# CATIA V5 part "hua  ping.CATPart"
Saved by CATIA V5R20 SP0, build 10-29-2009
Part number: Part2
Material "Blue Onyx": density 2770 kg/m3, Young's modulus 6e+10 Pa, Poisson ratio 0.27, thermal expansion 7e-06 1/K
Material "Grass": density 350 kg/m3
Bounding box of the stored display mesh (mm): x -46.351 to 39.989, y -39.989 to 39.949, z 0 to 161.792
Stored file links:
  C:\Users\HUAWEI\Desktop\hua  ping.CATPart
  D:\CATIA20\win_b64\startup\materials\Catalog.CATMaterial
  D:\CATIA20\win_b64\startup\materials\blue_onyx.jpg
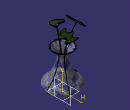
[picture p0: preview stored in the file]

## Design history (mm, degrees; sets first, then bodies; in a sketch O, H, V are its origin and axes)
Set1
  Plane1: type Offset, RefPlane xy-plane, Offset 20
  Plane2: type Offset, RefPlane Plane1, Offset 20
  Plane3: type Offset, RefPlane Plane2, Offset 20
  Plane4: type Offset, RefPlane Plane3, Offset 20
  Plane5: type Offset, RefPlane Plane4, Offset 20
  Sketch1 on xy-plane, origin (0, 0, 0), H (1, 0, 0), V (0, 1, 0)
    circle A1 centre (0, 0) radius 10
  Sketch2 on Plane1, origin (0, 0, 20), H (1, 0, 0), V (0, 1, 0)
    circle A1 centre (0, 0) radius 40
  Sketch3 on Plane2, origin (0, 0, 40), H (1, 0, 0), V (0, 1, 0)
    circle A1 centre (0, 0) radius 24
  Sketch4 on Plane3, origin (0, 0, 60), H (1, 0, 0), V (0, 1, 0)
    circle A1 centre (0, 0) radius 15
  Sketch5 on Plane4, origin (0, 0, 80), H (1, 0, 0), V (0, 1, 0)
    circle A1 centre (0, 0) radius 10
  Sketch6 on Plane5, origin (0, 0, 100), H (1, 0, 0), V (0, 1, 0)
    circle A1 centre (0, 0) radius 25
Body1 (main body), material "Blue Onyx"
  Loft1: solid, Sections (Sketch6; Sketch5; Sketch4; Sketch3; Sketch2; Sketch1)
  Shell1: IntOffset 1, Face face of Loft1, ExtOffset 0
  Sketch7 on yz-plane, origin (0, 0, 0), H (0, 1, 0), V (0, 0, 1)
    axis line L1 (0, 122.4223) -> (0, -28.4493)
  Sketch8 on yz-plane, origin (0, 0, 0), H (0, 1, 0), V (0, 0, 1)
    axis line L1 (0, 133.8174) -> (0, -23.2075)
  Sketch9 on yz-plane, origin (0, 0, 0), H (0, 1, 0), V (0, 0, 1)
    point P1 (0, 32.7739)
    line L1 (0, 32.7739) -> (22.7213, 32.7739)
    arc A1 centre (20.8479, 20.9105) radius 12.0104 from (22.7213, 32.7739) to (25.6844, 9.917) cw
    line L2 (25.6844, 9.917) -> (13.0754, 4.3697)
    line L3 (13.0754, 4.3697) -> (0, 4.3697)
    point P6 (0, 4.3697)
    coincidence: P1 V, P6 V
    horizontal: L1 H, L3 H
    tangency: L2 A1
  Shaft1: profile Sketch9, axis Sketch9.V, angle 360
Body2, material "Grass"
  Sketch10 on yz-plane, origin (0, 0, 0), H (0, 1, 0), V (0, 0, 1)
    spline S1 through (7.8895, 8.5551) (2.3376, 62.8541) (16.0968, 126.7636)
  Plane6: type Normal, Curve Sketch10, RefPoint vertex of Sketch10
  Sketch11 on Plane6, origin (0, 45.3156, 115.2778), H (1, 0, 0), V (0, -0.9307, 0.3658)
    circle A1 centre (0, 31.3229) radius 1
    point P1 (0, 31.3229)
    radius A1 = 1
    coincidence: P1 V
  Rib1: profile Sketch11, centre curve Sketch10
  Sketch12 on Plane6, origin (0, 45.3156, 115.2778), H (1, 0, 0), V (0, -0.9307, 0.3658)
    spline S1 through (-9.4387, 50.7533) (-6.6792, 39.3585) (-16.8312, 37.3892) (-6.6792, 28.5159) (-15.19, 22.2241) (-5.7623, 21.1075) (12.7661, 28.5159) (4.9438, 33.439) (18.498, 38.4462) (9.3577, 45.8065)
    spline S2 through (-9.4387, 50.7533) (0, 51.6086) (9.3577, 45.8065)
    point P1 (-9.4387, 50.7533)
    point P2 (-9.4387, 50.7533)
    point P3 (0, 51.6086)
    point P4 (9.3577, 45.8065)
    point P5 (9.3577, 45.8065)
    coincidence: P2 P1, P3 V, P4 P5
  Pad1: profile Sketch12, direction (0, 0.3658, 0.9307), length 2
  Sketch13 on yz-plane, origin (0, 0, 0), H (0, 1, 0), V (0, 0, 1)
    spline S1 through (-4.6889, 9.9662) (-2.2696, 50.6346) (-17.0542, 143.7438)
  Plane7: type Normal, Curve Sketch13, RefPoint vertex of Sketch13
  Sketch14 on Plane7, origin (0, -42.6157, 135.7174), H (1, 0, 0), V (0, 0.9541, 0.2996)
    circle A1 centre (0, 26.7645) radius 1
    point P1 (0, 26.7645)
    radius A1 = 1
    coincidence: P1 V
  Rib2: profile Sketch14, centre curve Sketch13
  Sketch15 on Plane7, origin (0, -42.6157, 135.7174), H (1, 0, 0), V (0, 0.9541, 0.2996)
    spline S1 through (0, 33.6334) (11.5555, 41.3304) (0, 12.0262) (-12.4268, 38.009) (0, 33.6334)
    point P1 (0, 33.6334)
    point P2 (0, 12.0262)
    point P3 (0, 33.6334)
    coincidence: P1 V, P2 V, P3 P1
  Pad2: profile Sketch15, direction (0, -0.2996, 0.9541), length 2
  Sketch16 on zx-plane, origin (0, 0, 0), H (-1, 0, 0), V (0, 0, 1)
    spline S1 through (8.0749, 17.0266) (2.7082, 71.4137) (35.884, 138.1835)
  Plane8: type Normal, Curve Sketch16, RefPoint vertex of Sketch16
  Sketch17 on Plane8, origin (-84.9042, 0, 93.8234), H (0, 1, 0), V (0.7415, 0, 0.671)
    circle A1 centre (0, 65.9655) radius 0.5
    point P1 (0, 65.9655)
    radius A1 = 0.5
    coincidence: P1 V
  Rib3: profile Sketch17, centre curve Sketch16
  Sketch18 on Plane8, origin (-84.9042, 0, 93.8234), H (0, 1, 0), V (0.7415, 0, 0.671)
    spline S1 through (5.7773, 82.2859) (2.4475, 97.1101) (0, 82.2859) (-5.6181, 82.2859) (-19.623, 76.3472) (-7.2758, 71.5861) (-3.4738, 63.1806) (6.9759, 54.409) (11.7202, 63.1806) (22.6393, 67.9153) (26.6729, 73.7892) (14.3258, 78.0741) (5.7773, 82.2859)
    point P1 (0, 82.2859)
    point P2 (5.7773, 82.2859)
    point P3 (5.7773, 82.2859)
    coincidence: P1 V, P2 P3
  Pad3: profile Sketch18, direction (-0.671, 0, 0.7415), length 2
